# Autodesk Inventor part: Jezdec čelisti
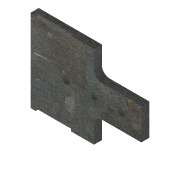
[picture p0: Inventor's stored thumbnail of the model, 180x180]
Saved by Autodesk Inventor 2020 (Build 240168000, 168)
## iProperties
Created: 2025-03
Part Number: Jezdec čelisti
Material: Ocel
Document SubType Name: Modeling
Designer: doma
Density: 7.85 g/cm^3
Appearance: Plech
Mass: 887.449 g
Surface Area: 282.372 cm^2
Volume: 113.051 cm^3
Author: doma
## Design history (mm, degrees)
sketch "Náčrt1"
  geometry: L1 (0, 0)-(80, 0); L2 (80, 0)-(80, 32.5); L3 (80, 32.5)-(140, 32.5); L4 (0, 0)-(0, 105); L5 (140, 32.5)-(140, 72.5); L6 (140, 72.5)-(80, 72.5); L7 (80, 72.5)-(80, 105); L8 (80, 105)-(0, 105)
  constraints: 16 end point, 4 perpendicular, 2 vertical, 1 horizontal, 1 parallel
  dimensions: "d0" = 80 distance of L1.start L1.end; "d1" = 60 distance of L2.end L3.end; "d2" = 105 distance of L1.start L4.end; "d3" = 40 distance of L3.end L5.end; "d4" = 32.5 distance of L6.end L7.end
extrude "Vysunutí1" new body sketch "Náčrt1" distance "d5" = 10; taper "d6" = 0 deg
sketch "Náčrt2"
  geometry: L1 (140, 32.5)-(140, 72.5) reference; L2 (0, 105)-(0, 0) reference; L3 (80, 72.5)-(80, 105) reference; 3 further points
  dimensions: "d9" = 35 distance of point (45, 52.5) point (80, 52.5); "d10" = 35 distance of point (115, 52.5) point (80, 52.5)
hole "Díra1" sketch "Náčrt2" at (80, 52.5), (45, 52.5), (115, 52.5) diameter "d11" = 6; stored, may be unused: countersink angle "d15" = 90 deg, drill point angle "d17" = 118 deg; dims "d12" = 10, "d13" = 9, "d14" = 5, "d16" = 8
fillet "Zaoblení1" dims "d18" = 10
chamfer "Zkosení1" distance "d19" = 3; stored, may be unused: second distance "d20" = 2, angle "d21" = 45 deg; dims "d22" = 6, "d23" = 45, "d24" = 29
chamfer "Zkosení2" distance "d25" = 3; stored, may be unused: second distance "d26" = 2, angle "d27" = 45 deg; dims "d28" = 29, "d29" = 45, "d30" = 6
node "Těleso1"
